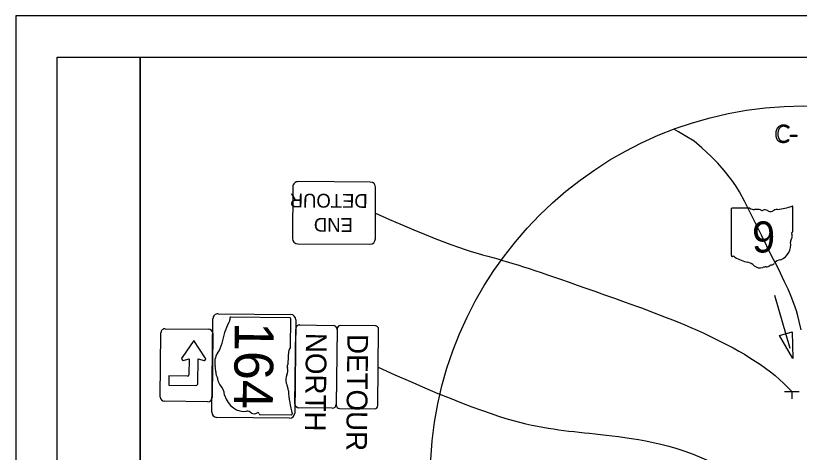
# Model space of a CAD drawing. Extents: x -202 to 1556, y 0 to 676.
# Drawn here: x 0 to 189, y 334.7 to 440 of the extents above; entities that cross this region are included whole.
import ezdxf

# ---------------------------------------------------------------- set-up
doc = ezdxf.new("R2010")
doc.units = 0
for name, color, linetype in [('Default', 7, 'Continuous'), ('GM_X_City_Street', 7, 'Continuous'), ('GM_X_Minor_Lake', 7, 'Continuous'), ('GM_X_State_Location', 7, 'Continuous'), ('SH_Border', 7, 'Continuous'), ('SH_Cut_Line', 7, 'Continuous'), ('SH_Data', 7, 'Continuous')]:
    doc.layers.add(name, color=color, linetype=linetype)

msp = doc.modelspace()

# ---------------------------------------------------------------- linework, layer by layer
at = {"layer": 'Default'}
msp.add_line((186.8, 359.7), (183.17, 372.5), dxfattribs=at)
msp.add_lwpolyline([(189.45, 364.19), (189.01, 366.24), (188.7, 367.57), (188.33, 368.84), (187.74, 370.58), (187.1, 372.29), (186.32, 374.06), (185.48, 375.82), (184.48, 377.88), (183.58, 379.73), (182.44, 381.93), (179.89, 387.02), (175.85, 395.28), (174.62, 397.5), (173.69, 398.99), (172.75, 400.36), (170.91, 402.68), (169.4, 404.4), (167.8, 406.04), (165.56, 408.09), (163.65, 409.71), (161.52, 411.02), (159.91, 411.97), (158.75, 412.62)], dxfattribs=at)
msp.add_lwpolyline([(187.28, 363.73), (187.48, 357.3), (184.27, 362.88)], close=True, dxfattribs=at)
at = {"layer": 'GM_X_City_Street'}
for p, q in [((172.63, 393.39), (172.63, 382.14)), ((177.12, 393.59), (172.78, 393.59)), ((187.47, 387.98), (187.47, 393.87)), ((187.46, 387.98), (187.47, 387.98))]:
    msp.add_line(p, q, dxfattribs=at)
for centre, radius, start, end in [((172.8, 393.42), 0.172, 98.1301, 188.1301), ((178.16, 394.89), 1.67, 231.6195, 271.1119), ((178.71, 387.27), 5.98, 80.4867, 94.9883), ((184.19, 390.15), 3.16, 97.3462, 120.7689), ((182.18, 408.93), 15.73, 275.8445, 288.9065), ((187.3, 393.89), 0.165, 351.8621, 97.738), ((180.07, 393.48), 0.481, 219.7921, 297.1024), ((180.78, 392.18), 1, 54.4667, 119.1411), ((182.07, 393.96), 1.2, 233.8562, 294.8282), ((187.43, 387.55), 0.256, 107.944, 210.337), ((187.29, 387.96), 0.177, 289.6038, 7.7341), ((188.06, 385.51), 1.12, 136.8065, 186.9296), ((185.8, 386.8), 1.53, 340.033, 23.6496), ((183.06, 384.77), 3.93, 292.3089, 8.9858), ((172.81, 382.11), 0.173, 171.9584, 258.3066), ((172.83, 383.26), 1.32, 267.339, 280.6039), ((173.1, 381.49), 0.477, 29.7484, 93.2717), ((179.13, 391.6), 11.36, 240.4129, 257.1985), ((175.74, 377.08), 3.55, 47.1842, 75.836), ((181.99, 381.05), 1.27, 282.8732, 323.2771), ((184.72, 378.98), 2.15, 94.4031, 142.5768), ((179.58, 381.43), 2.26, 230.7004, 286.2918), ((180.89, 377.54), 1.85, 85.6951, 111.2099), ((181.05, 380.59), 1.2, 268.777, 315.5493), ((182.14, 379.5), 0.338, 65.7517, 132.6484)]:
    msp.add_arc(centre, radius, start, end, dxfattribs=at)
at = {"layer": 'GM_X_Minor_Lake'}
for p, q in [((66.11, 367.14), (51.88, 367.3)), ((66.27, 360.04), (66.35, 366.9)), ((68.56, 365.39), (76.56, 365.3)), ((34.86, 348.02), (35.04, 363.52)), ((36.05, 364.5), (46.55, 364.39)), ((47.54, 363.38), (47.36, 347.88)), ((67.35, 346.4), (67.55, 364.4)), ((77.55, 364.29), (77.35, 346.29)), ((42.98, 361.61), (40.14, 357.56)), ((45.73, 357.5), (42.98, 361.61)), ((40.43, 356.85), (41.84, 357.25)), ((41.84, 357.25), (41.8, 353.34)), ((43.96, 351.29), (44.03, 357.23)), ((44.03, 357.23), (45.43, 356.79)), ((36.95, 353.09), (36.93, 350.9)), ((41.48, 353.04), (36.95, 353.09)), ((36.93, 350.9), (43.49, 350.82)), ((43.96, 351.29), (43.96, 351.29)), ((185.43, 349.35), (189.03, 349.33)), ((187.23, 349.34), (187.22, 347.54)), ((46.35, 346.89), (35.85, 347.01)), ((76.34, 345.3), (68.34, 345.39)), ((59, 343.78), (66.44, 343.69)), ((59, 343.78), (59, 343.78))]:
    msp.add_line(p, q, dxfattribs=at)
for points in [[(85.55, 399.87), (68.15, 399.98)], [(66.84, 398.69), (66.76, 386.29)], [(86.76, 386.16), (86.84, 398.56)], [(68.05, 384.98), (85.45, 384.87)], [(47.32, 344.38), (47.58, 366.88)], [(48.84, 368.11), (66.34, 367.92)], [(67.57, 366.65), (67.32, 344.15)], [(86.76, 365.19), (78.36, 365.28)], [(77.55, 364.49), (77.34, 346.09)], [(87.34, 345.98), (87.55, 364.38)], [(78.14, 345.28), (86.54, 345.19)], [(66.06, 342.92), (48.56, 343.11)]]:
    msp.add_lwpolyline(points, dxfattribs=at)
for centre, radius, start, end in [((68.14, 398.68), 1.3, 89.6227, 179.6227), ((85.54, 398.57), 1.3, 359.6227, 89.6227), ((68.06, 386.28), 1.3, 179.6227, 269.6227), ((85.46, 386.17), 1.3, 269.6227, 359.6227), ((48.83, 366.86), 1.25, 89.359, 179.359), ((66.32, 366.67), 1.25, 359.359, 89.359), ((68.55, 364.39), 1, 89.359, 179.359), ((76.55, 364.3), 1, 359.359, 89.359), ((78.35, 364.48), 0.8, 89.359, 179.359), ((86.75, 364.39), 0.8, 359.359, 89.359), ((36.04, 363.5), 1, 89.359, 179.359), ((46.54, 363.39), 1, 359.359, 89.359), ((40.44, 357.27), 0.417, 134.3591, 269.3606), ((45.44, 357.21), 0.417, 269.3606, 44.3588), ((41.48, 353.35), 0.312, 269.359, 359.359), ((43.49, 351.29), 0.469, 269.359, 359.359), ((35.86, 348.01), 1, 179.359, 269.359), ((46.36, 347.89), 1, 269.359, 359.359), ((68.35, 346.39), 1, 179.359, 269.359), ((76.35, 346.3), 1, 269.359, 359.359), ((78.14, 346.08), 0.8, 179.359, 269.359), ((86.54, 345.99), 0.8, 269.359, 359.359), ((48.57, 344.36), 1.25, 179.359, 269.359), ((66.07, 344.17), 1.25, 269.359, 359.359)]:
    msp.add_arc(centre, radius, start, end, dxfattribs=at)
for centre, major_axis, start_param, end_param in [((53.3, 366.97), (-0.02, -2.09), 4.665946, 4.897461), ((51.84, 367.03), (-0.003, -0.274), 3.00124, 4.508301), ((66.14, 366.87), (-0.003, -0.271), 1.712693, 3.28349), ((63.73, 356.91), (-0.2, -17.95), 4.195997, 4.488961), ((51.05, 366.57), (-0.008, -0.754), 0.519207, 1.627899), ((45.43, 362.46), (-0.06, -5.62), 0.823519, 1.323587), ((67.91, 358.39), (-0.03, -2.63), 4.042523, 4.731795), ((50.86, 356.33), (-0.04, -3.56), 4.026481, 4.996735), ((58.26, 357.62), (-0.11, -9.45), 1.404758, 1.657858), ((66.08, 355.39), (-0.009, -0.76), 3.836095, 5.185415), ((45.92, 354.32), (-0.03, -2.93), 1.495662, 1.94098), ((49.77, 354.02), (-0.02, -1.9), 4.691044, 5.507374), ((64.42, 354.29), (-0.02, -1.58), 0.950623, 2.079405), ((48.37, 352.32), (-0.006, -0.535), 1.147584, 2.315152), ((50.33, 352.52), (-0.02, -2.01), 4.937069, 5.64225), ((66.66, 352.23), (-0.02, -1.9), 4.081561, 5.145723), ((47.67, 348.24), (-0.04, -3.4), 1.647645, 2.488434), ((61.8, 348.93), (-0.06, -5), 1.699011, 2.107814), ((55.01, 350.78), (-0.07, -6.22), 5.101752, 6.440018), ((85.58, 351.83), (-0.28, -24.85), 4.814394, 5.042369), ((55.87, 342.88), (-0.02, -1.76), 2.387724, 3.262537), ((57.54, 346.42), (-0.03, -2.42), 5.934695, 6.695948), ((58.45, 343.84), (-0.005, -0.404), 1.883978, 3.671073), ((58.97, 344.06), (-0.003, -0.279), 5.05454, 6.418171), ((66.48, 343.95), (-0.003, -0.261), 6.141152, 7.989035)]:
    msp.add_ellipse(centre, major_axis=major_axis, ratio=0.8, start_param=start_param, end_param=end_param, dxfattribs=at)
at = {"layer": 'GM_X_State_Location'}
for p, q in [((188.37, 410.83), (186.99, 410.86)), ((187, 411.19), (188.37, 411.16)), ((188.47, 411), (188.47, 411)), ((186.44, 409.95), (186.44, 409.95))]:
    msp.add_line(p, q, dxfattribs=at)
for points in [[(183.42, 411.49), (183.43, 412.01), (183.57, 412.42)], [(183.57, 412.42), (183.71, 412.83), (183.95, 413.11)], [(183.97, 412.29), (183.86, 411.95), (183.85, 411.51)], [(183.95, 413.11), (184.19, 413.39), (184.53, 413.54)], [(184.26, 412.86), (184.07, 412.63), (183.97, 412.29)], [(184.69, 413.21), (184.44, 413.09), (184.26, 412.86)], [(184.53, 413.54), (184.86, 413.69), (185.27, 413.68)], [(185.24, 413.32), (184.94, 413.32), (184.69, 413.21)], [(185.71, 413.24), (185.51, 413.31), (185.24, 413.32)], [(185.27, 413.68), (185.46, 413.68), (185.63, 413.64)], [(185.63, 413.64), (185.81, 413.6), (185.96, 413.54)], [(186.04, 413.08), (185.9, 413.17), (185.71, 413.24)], [(185.96, 413.54), (186.11, 413.48), (186.23, 413.41)], [(186.25, 412.93), (186.17, 413), (186.04, 413.08)], [(186.23, 413.41), (186.35, 413.33), (186.39, 413.29)], [(186.38, 412.86), (186.34, 412.86), (186.25, 412.93)], [(186.42, 412.87), (186.41, 412.86), (186.38, 412.86)], [(186.39, 413.29), (186.44, 413.24), (186.45, 413.22)], [(186.45, 412.91), (186.44, 412.89), (186.42, 412.87)], [(186.45, 413.22), (186.46, 413.2), (186.46, 413.18)], [(186.47, 412.97), (186.46, 412.94), (186.45, 412.91)], [(186.46, 413.18), (186.47, 413.15), (186.47, 413.12)], [(186.47, 413.12), (186.47, 413.09), (186.47, 413.05)], [(186.47, 413.05), (186.47, 413), (186.47, 412.97)], [(183.53, 410.59), (183.41, 410.99), (183.42, 411.49)], [(183.87, 409.92), (183.64, 410.19), (183.53, 410.59)], [(183.85, 411.51), (183.85, 411.09), (183.93, 410.76)], [(183.93, 410.76), (184.02, 410.43), (184.19, 410.2)], [(186.9, 411.02), (186.9, 411.12), (186.93, 411.15)], [(186.92, 410.9), (186.9, 410.93), (186.9, 411.02)], [(186.99, 410.86), (186.95, 410.86), (186.92, 410.9)], [(186.93, 411.15), (186.96, 411.19), (187, 411.19)], [(188.37, 411.16), (188.39, 411.16), (188.41, 411.15)], [(188.44, 410.87), (188.41, 410.83), (188.37, 410.83)], [(188.41, 411.15), (188.43, 411.14), (188.44, 411.12)], [(188.44, 411.12), (188.46, 411.1), (188.46, 411.07)], [(188.47, 411), (188.46, 410.9), (188.44, 410.87)], [(188.46, 411.07), (188.47, 411.04), (188.47, 411)], [(184.41, 409.5), (184.09, 409.65), (183.87, 409.92)], [(184.19, 410.2), (184.36, 409.97), (184.61, 409.85)], [(185.13, 409.35), (184.73, 409.36), (184.41, 409.5)], [(184.61, 409.85), (184.86, 409.73), (185.19, 409.72)], [(185.59, 409.39), (185.38, 409.35), (185.13, 409.35)], [(185.19, 409.72), (185.45, 409.72), (185.65, 409.78)], [(185.96, 409.5), (185.8, 409.44), (185.59, 409.39)], [(185.65, 409.78), (185.85, 409.84), (186, 409.92)], [(186.22, 409.64), (186.12, 409.57), (185.96, 409.5)], [(186, 409.92), (186.14, 410), (186.23, 410.07)], [(186.36, 409.74), (186.33, 409.71), (186.22, 409.64)], [(186.23, 410.07), (186.32, 410.13), (186.37, 410.13)], [(186.4, 409.79), (186.39, 409.77), (186.36, 409.74)], [(186.37, 410.13), (186.39, 410.13), (186.4, 410.12)], [(186.4, 410.12), (186.42, 410.12), (186.42, 410.09)], [(186.42, 409.83), (186.42, 409.81), (186.4, 409.79)], [(186.42, 410.09), (186.43, 410.07), (186.44, 410.04)], [(186.43, 409.88), (186.43, 409.85), (186.42, 409.83)], [(186.44, 409.95), (186.44, 409.91), (186.43, 409.88)], [(186.44, 410.04), (186.44, 410), (186.44, 409.95)]]:
    msp.add_open_spline(points, degree=2, dxfattribs=at)
at = {"layer": 'SH_Border'}
for points in [[(10, 430), (30, 430), (30, 10), (10, 10)], [(30, 430), (670, 430), (670, 10), (30, 10)]]:
    msp.add_lwpolyline(points, close=True, dxfattribs=at)
at = {"layer": 'SH_Cut_Line'}
msp.add_lwpolyline([(0, 0), (680, 0), (680, 440), (0, 440)], close=True, dxfattribs=at)
at = {"layer": 'SH_Data'}
msp.add_circle((190, 328.22), 90, dxfattribs=at)
for points in [[(86.8, 392.36), (105.56, 383.91), (116.65, 381.7), (138.18, 374.08), (177.66, 360), (187.23, 349.34)], [(87.45, 355.18), (109.77, 345.09), (127.6, 339.7), (143.95, 339.31), (166.86, 334.83), (177.92, 325.73)]]:
    msp.add_open_spline(points, degree=3, dxfattribs=at)

# ---------------------------------------------------------------- texts
at = {"layer": 'GM_X_City_Street'}
msp.add_text('9', height=7.5, dxfattribs=at).set_placement((177.63, 382.87))
at = {"layer": 'GM_X_Minor_Lake'}
for s, height, rotation, p in [('DETOUR', 3.333, 179.6227, (84.93, 396.96)), ('END', 3.333, 179.6227, (81.36, 391.17)), ('164', 9.375, 269.359, (52.87, 366.14)), ('NORTH', 5, 269.359, (70.04, 363.51)), ('DETOUR', 5, 269.359, (80.04, 363.23))]:
    msp.add_text(s, height=height, rotation=rotation, dxfattribs=at).set_placement(p)

doc.saveas('drawing.dxf')
